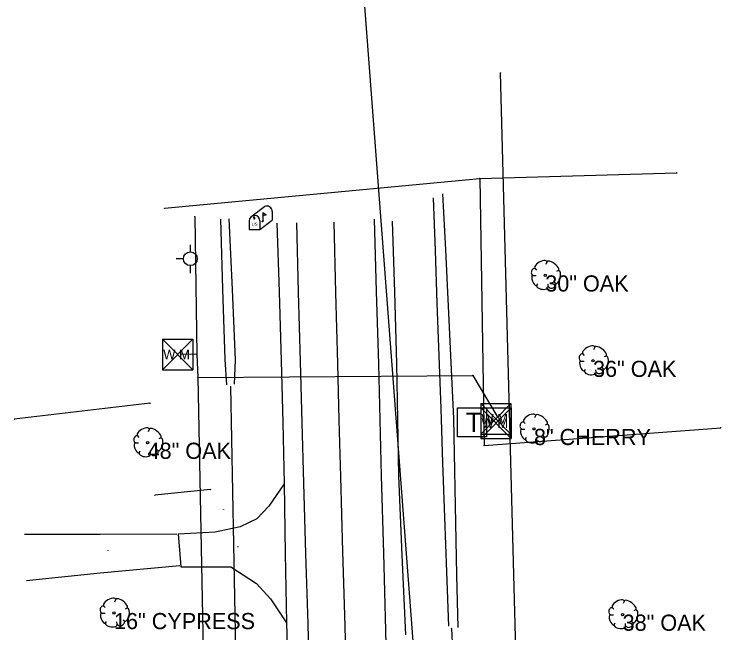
# Model space of a CAD drawing. Extents: x 1930288 to 1941089, y 588389 to 611475.
# Drawn here: x 1930817.5 to 1931036, y 599091.7 to 599283.2 of the extents above; entities that cross this region are included whole.
import ezdxf

# ---------------------------------------------------------------- set-up
doc = ezdxf.new("R2010")
doc.units = 0
for name, color, linetype in [('S_BASELINE', 7, 'Continuous'), ('S_DITCHLINE', 7, 'Continuous'), ('S_DRG_PT_SYM', 7, 'Continuous'), ('S_DRIVEWAY', 7, 'Continuous'), ('S_EDGE_CONCRETE', 7, 'Continuous'), ('S_EDGE_PAVEMENT', 7, 'Continuous'), ('S_GAS_UTILITIES', 7, 'Continuous'), ('S_MAILBOX', 7, 'Continuous'), ('S_MSC_PT_SYM', 7, 'Continuous'), ('S_PAVEMENT_CROWN', 7, 'Continuous'), ('S_SANITARY_SEWER', 7, 'Continuous'), ('S_SHOULDER', 7, 'Continuous'), ('S_SIDE_DRAIN', 7, 'Continuous'), ('S_TELEPHONE_UTILITIES', 7, 'Continuous'), ('S_TREE', 7, 'Continuous'), ('S_TREE_ANNOT', 7, 'Continuous'), ('S_UTILITY_POLE', 7, 'Continuous'), ('S_UTL_PT_SYM', 7, 'Continuous'), ('S_WATER_UTILITIES', 7, 'Continuous')]:
    doc.layers.add(name, color=color, linetype=linetype)

msp = doc.modelspace()

# ---------------------------------------------------------------- linework, layer by layer
at = {"layer": 'S_BASELINE'}
msp.add_line((1930946.09, 599020.44), (1930874, 599969.55), dxfattribs=at)
at = {"layer": 'S_DITCHLINE'}
for points in [[(1930949.94, 599227.59), (1930950.79, 599210.21), (1930951.65, 599192.82), (1930952.5, 599175.44), (1930953.35, 599158.06), (1930953.66, 599141.89), (1930953.97, 599125.73), (1930954.29, 599109.56), (1930954.6, 599093.39)], [(1930951.87, 599093.81), (1930951.27, 599110.66), (1930950.66, 599127.51), (1930950.05, 599144.35), (1930949.45, 599161.2), (1930948.87, 599177.5), (1930948.3, 599193.8), (1930947.72, 599210.1), (1930947.15, 599226.39)], [(1930881.27, 599219.76), (1930881.94, 599198.06), (1930882.62, 599176.35), (1930883.17, 599168.44)], [(1930883.88, 599219.85), (1930884.86, 599198.03), (1930885.84, 599176.21), (1930885.5, 599168.66)]]:
    msp.add_lwpolyline(points, dxfattribs=at)
at = {"layer": 'S_DRG_PT_SYM'}
for points in [[(1930884.4, 599167.97), (1930884.4, 599168.02), (1930884.4, 599167.97), (1930884.35, 599167.97), (1930884.4, 599167.97), (1930884.4, 599167.92), (1930884.4, 599167.97), (1930884.45, 599167.97)], [(1930952.67, 599093.04), (1930952.67, 599093.09), (1930952.67, 599093.04), (1930952.62, 599093.04), (1930952.67, 599093.04), (1930952.67, 599092.99), (1930952.67, 599093.04), (1930952.72, 599093.04)]]:
    msp.add_lwpolyline(points, dxfattribs=at)
at = {"layer": 'S_DRIVEWAY'}
msp.add_lwpolyline([(1930900.96, 599137.81), (1930896.26, 599130.93), (1930892.54, 599127.06), (1930887.31, 599124.51), (1930879.65, 599122.87), (1930868.17, 599122.32), (1930868.64, 599117.39), (1930868.96, 599112.21), (1930884.48, 599112.12), (1930892.44, 599106.96), (1930896.71, 599102.29), (1930901.66, 599094.84)], dxfattribs=at)
at = {"layer": 'S_EDGE_CONCRETE'}
for points in [[(1930867.74, 599122.23), (1930844.04, 599122.22), (1930820.71, 599122.19)], [(1930821.26, 599107.91), (1930844.04, 599110.3), (1930868.67, 599112.58)]]:
    msp.add_lwpolyline(points, dxfattribs=at)
at = {"layer": 'S_EDGE_PAVEMENT'}
for points in [[(1930904.72, 599218.64), (1930905.3, 599197.16), (1930905.89, 599175.68), (1930906.4, 599156.86), (1930906.92, 599138.04), (1930907.58, 599116.33), (1930908.24, 599094.62), (1930908.7, 599076.29)], [(1930928.79, 599219.79), (1930929.44, 599197.4), (1930930.09, 599175.01), (1930930.52, 599157.68), (1930930.96, 599140.35), (1930931.64, 599116.39), (1930932.32, 599092.44), (1930932.75, 599074.74)]]:
    msp.add_lwpolyline(points, dxfattribs=at)
at = {"layer": 'S_GAS_UTILITIES'}
for p, q in [((1930961.45, 599232.36), (1931022.34, 599234.07)), ((1930864.01, 599223.13), (1930961.45, 599232.36)), ((1930961.45, 599232.36), (1930962.79, 599149.74)), ((1930962.79, 599149.74), (1931035.92, 599155.19)), ((1930878.21, 599136.1), (1930860.97, 599134.33))]:
    msp.add_line(p, q, dxfattribs=at)
at = {"layer": 'S_MAILBOX'}
for p, q in [((1930890.7, 599220.51), (1930894.83, 599223.62)), ((1930894.32, 599221.8), (1930894.32, 599219.09)), ((1930897.27, 599222.15), (1930897.27, 599219.43)), ((1930890.15, 599219.24), (1930890.15, 599216.52)), ((1930893.47, 599216.52), (1930897.27, 599219.43)), ((1930893.47, 599219.24), (1930893.47, 599216.52)), ((1930890.15, 599216.52), (1930893.47, 599216.52))]:
    msp.add_line(p, q, dxfattribs=at)
for points in [[(1930891.33, 599220.35), (1930891.55, 599220.21), (1930891.55, 599219.83), (1930891.86, 599219.83), (1930891.86, 599220.19), (1930891.66, 599220.44), (1930891.33, 599220.38)], [(1930894.32, 599221.8), (1930895.42, 599221.14), (1930894.32, 599220.79)]]:
    msp.add_lwpolyline(points, dxfattribs=at)
for centre, end in [((1930895.6, 599222.15), 117.5718), ((1930891.81, 599219.24), 180)]:
    msp.add_arc(centre, 1.66, 0, end, dxfattribs=at)
msp.add_ellipse((1930894.32, 599219.09), major_axis=(0.145, 0.132), ratio=0.564646, dxfattribs=at)
at = {"layer": 'S_MSC_PT_SYM'}
for points in [[(1930859.48, 599162.79), (1930859.48, 599162.84), (1930859.48, 599162.79), (1930859.43, 599162.79), (1930859.48, 599162.79), (1930859.48, 599162.74), (1930859.48, 599162.79), (1930859.53, 599162.79)], [(1930817.52, 599157.86), (1930817.52, 599157.91), (1930817.52, 599157.86), (1930817.47, 599157.86), (1930817.52, 599157.86), (1930817.52, 599157.81), (1930817.52, 599157.86), (1930817.57, 599157.86)], [(1930846.44, 599117.27), (1930846.44, 599117.32), (1930846.44, 599117.27), (1930846.39, 599117.27), (1930846.44, 599117.27), (1930846.44, 599117.22), (1930846.44, 599117.27), (1930846.49, 599117.27)], [(1930886.68, 599118.36), (1930886.68, 599118.41), (1930886.68, 599118.36), (1930886.63, 599118.36), (1930886.68, 599118.36), (1930886.68, 599118.31), (1930886.68, 599118.36), (1930886.73, 599118.36)]]:
    msp.add_lwpolyline(points, dxfattribs=at)
at = {"layer": 'S_PAVEMENT_CROWN'}
msp.add_lwpolyline([(1930916.29, 599218.8), (1930916.85, 599196.95), (1930917.41, 599175.1), (1930917.89, 599157.55), (1930918.37, 599139.99), (1930919.03, 599116.95), (1930919.68, 599093.9), (1930920.14, 599075.83)], dxfattribs=at)
at = {"layer": 'S_SANITARY_SEWER'}
msp.add_line((1930979.26, 598838.38), (1930967.81, 599265.02), dxfattribs=at)
at = {"layer": 'S_SHOULDER'}
for points in [[(1930898.7, 599218.51), (1930899.39, 599197.23), (1930900.07, 599175.94), (1930900.52, 599156.88), (1930900.96, 599137.81), (1930901.31, 599116.32), (1930901.66, 599094.84), (1930902.24, 599076.43)], [(1930934.34, 599219.18), (1930935.02, 599197.13), (1930935.7, 599175.08), (1930935.99, 599157.72), (1930936.28, 599140.36), (1930937.38, 599115.75), (1930938.49, 599091.15)]]:
    msp.add_lwpolyline(points, dxfattribs=at)
at = {"layer": 'S_SIDE_DRAIN'}
for p, q in [((1930884.4, 599167.97), (1930886.94, 599030.09)), ((1930952.67, 599093.04), (1930953.96, 599068.83))]:
    msp.add_line(p, q, dxfattribs=at)
at = {"layer": 'S_TELEPHONE_UTILITIES'}
msp.add_lwpolyline([(1930954.56, 599152.37), (1930954.56, 599161.37), (1930963.56, 599161.37), (1930963.56, 599152.37)], close=True, dxfattribs=at)
at = {"layer": 'S_TREE'}
for p, q in [((1930982.23, 599206.61), (1930981.84, 599205.75)), ((1930978.43, 599204.59), (1930978.93, 599204.01)), ((1930985.79, 599203.82), (1930985.13, 599203.54)), ((1930977.77, 599202.27), (1930978.89, 599202.27)), ((1930978.93, 599199.09), (1930979.4, 599199.79)), ((1930982.61, 599198.82), (1930982.54, 599199.59)), ((1930985.02, 599199.71), (1930984.55, 599200.13)), ((1930997, 599180.18), (1930996.61, 599179.33)), ((1930993.2, 599178.16), (1930993.71, 599177.58)), ((1931000.57, 599177.39), (1930999.91, 599177.12)), ((1930992.55, 599175.84), (1930993.67, 599175.84)), ((1930993.71, 599172.66), (1930994.17, 599173.36)), ((1930997.39, 599172.39), (1930997.31, 599173.16)), ((1930999.79, 599173.28), (1930999.33, 599173.71)), ((1930859.48, 599162.79), (1930817.52, 599157.86)), ((1930978.73, 599159.09), (1930978.35, 599158.24)), ((1930974.94, 599157.08), (1930975.44, 599156.5)), ((1930859.29, 599154.83), (1930858.9, 599153.97)), ((1930974.28, 599154.75), (1930975.4, 599154.75)), ((1930982.3, 599156.3), (1930981.64, 599156.03)), ((1930855.49, 599152.81), (1930855.99, 599152.23)), ((1930975.44, 599151.57), (1930975.9, 599152.27)), ((1930981.52, 599152.19), (1930981.06, 599152.62)), ((1930854.83, 599150.49), (1930855.95, 599150.49)), ((1930862.85, 599152.04), (1930862.19, 599151.77)), ((1930979.12, 599151.3), (1930979.04, 599152.08)), ((1930855.99, 599147.31), (1930856.46, 599148.01)), ((1930862.08, 599147.93), (1930861.61, 599148.36)), ((1930859.67, 599147.04), (1930859.6, 599147.81)), ((1930848.9, 599102.12), (1930848.51, 599101.27)), ((1930845.1, 599100.11), (1930845.61, 599099.53)), ((1931006.15, 599101.63), (1931005.76, 599100.77)), ((1930844.44, 599097.78), (1930845.57, 599097.78)), ((1930852.46, 599099.33), (1930851.81, 599099.06)), ((1931002.35, 599099.61), (1931002.85, 599099.03)), ((1931009.71, 599098.84), (1931009.05, 599098.57)), ((1930851.69, 599095.23), (1930851.22, 599095.65)), ((1931001.69, 599097.29), (1931002.82, 599097.29)), ((1930845.61, 599094.61), (1930846.07, 599095.3)), ((1930849.29, 599094.34), (1930849.21, 599095.11)), ((1931002.85, 599094.11), (1931003.32, 599094.81)), ((1931006.54, 599093.84), (1931006.46, 599094.61)), ((1931008.94, 599094.73), (1931008.47, 599095.16))]:
    msp.add_line(p, q, dxfattribs=at)
for centre in [(1930981.67, 599202.36), (1930996.44, 599175.93), (1930978.17, 599154.85), (1930858.73, 599150.58), (1930848.34, 599097.88), (1931005.59, 599097.38)]:
    msp.add_circle(centre, 0.341, dxfattribs=at)
for centre, major_axis, ratio, start_param, end_param in [((1930980.33, 599205.56), (1.86, 1.08), 0.471018, 0, 3.141593), ((1930983.99, 599205.24), (-1.81, 1.36), 0.405113, 3.141593, 6.283186), ((1930978.1, 599203.45), (0.31, 1.03), 0.646762, 0, 3.141593), ((1930985.34, 599201.83), (0.46, 2.04), 0.482994, 3.141593, 6.283185), ((1930978.4, 599200.8), (-0.61, 1.6), 0.420543, 6.283185, 9.424777), ((1930980.86, 599199.02), (-1.83, 0.19), 0.529943, 0, 3.141593), ((1930983.82, 599199.31), (1.09, 0.46), 0.711534, 3.141592, 6.283185), ((1930995.11, 599179.14), (1.86, 1.08), 0.471018, 0, 3.141593), ((1930998.76, 599178.81), (-1.81, 1.36), 0.405113, 3.141593, 6.283186), ((1930992.87, 599177.02), (0.31, 1.03), 0.646762, 0, 3.141593), ((1931000.12, 599175.4), (0.46, 2.04), 0.482994, 3.141593, 6.283185), ((1930993.18, 599174.37), (-0.61, 1.6), 0.420543, 6.283185, 9.424777), ((1930995.64, 599172.59), (-1.83, 0.19), 0.529943, 0, 3.141593), ((1930998.6, 599172.88), (1.09, 0.46), 0.711534, 3.141592, 6.283185), ((1930976.84, 599158.05), (1.86, 1.08), 0.471018, 0, 3.141593), ((1930980.49, 599157.73), (-1.81, 1.36), 0.405113, 3.141593, 6.283186), ((1930974.6, 599155.93), (0.31, 1.03), 0.646762, 0, 3.141593), ((1930857.39, 599153.78), (1.86, 1.08), 0.471018, 0, 3.141593), ((1930861.05, 599153.46), (-1.81, 1.36), 0.405113, 3.141593, 6.283186), ((1930974.91, 599153.28), (-0.61, 1.6), 0.420543, 6.283185, 9.424777), ((1930981.85, 599154.32), (0.46, 2.04), 0.482994, 3.141593, 6.283185), ((1930855.16, 599151.67), (0.31, 1.03), 0.646762, 0, 3.141593), ((1930980.33, 599151.8), (1.09, 0.46), 0.711534, 3.141592, 6.283185), ((1930855.46, 599149.02), (-0.61, 1.6), 0.420543, 6.283185, 9.424777), ((1930862.4, 599150.05), (0.46, 2.04), 0.482994, 3.141593, 6.283185), ((1930977.37, 599151.5), (-1.83, 0.19), 0.529943, 0, 3.141593), ((1930860.88, 599147.53), (1.09, 0.46), 0.711534, 3.141592, 6.283185), ((1930857.92, 599147.24), (-1.83, 0.19), 0.529943, 0, 3.141593), ((1930847, 599101.08), (1.86, 1.08), 0.471018, 0, 3.141593), ((1930850.66, 599100.76), (-1.81, 1.36), 0.405113, 3.141593, 6.283186), ((1931004.25, 599100.58), (1.86, 1.08), 0.471018, 0, 3.141593), ((1931007.91, 599100.26), (-1.81, 1.36), 0.405113, 3.141593, 6.283186), ((1930844.77, 599098.97), (0.31, 1.03), 0.646762, 0, 3.141593), ((1930845.08, 599096.32), (-0.61, 1.6), 0.420543, 6.283185, 9.424777), ((1930852.02, 599097.35), (0.46, 2.04), 0.482994, 3.141593, 6.283185), ((1931002.02, 599098.47), (0.31, 1.03), 0.646762, 0, 3.141593), ((1931009.26, 599096.85), (0.46, 2.04), 0.482994, 3.141593, 6.283185), ((1931002.32, 599095.82), (-0.61, 1.6), 0.420543, 6.283185, 9.424777), ((1930847.54, 599094.54), (-1.83, 0.19), 0.529943, 0, 3.141593), ((1930850.49, 599094.83), (1.09, 0.46), 0.711534, 3.141592, 6.283185), ((1931004.79, 599094.04), (-1.83, 0.19), 0.529943, 0, 3.141593), ((1931007.74, 599094.33), (1.09, 0.46), 0.711534, 3.141592, 6.283185)]:
    msp.add_ellipse(centre, major_axis=major_axis, ratio=ratio, start_param=start_param, end_param=end_param, dxfattribs=at)
at = {"layer": 'S_UTILITY_POLE'}
for p, q in [((1930871.95, 599209.6), (1930871.95, 599211.85)), ((1930869.86, 599207.47), (1930867.53, 599207.47)), ((1930872.03, 599203.05), (1930872.03, 599205.38))]:
    msp.add_line(p, q, dxfattribs=at)
msp.add_circle((1930871.95, 599207.49), 2.13, dxfattribs=at)
at = {"layer": 'S_UTL_PT_SYM'}
for points in [[(1930967.81, 599265.02), (1930967.81, 599265.07), (1930967.81, 599265.02), (1930967.76, 599265.02), (1930967.81, 599265.02), (1930967.81, 599264.97), (1930967.81, 599265.02), (1930967.86, 599265.02)], [(1931022.34, 599234.07), (1931022.34, 599234.12), (1931022.34, 599234.07), (1931022.29, 599234.07), (1931022.34, 599234.07), (1931022.34, 599234.02), (1931022.34, 599234.07), (1931022.39, 599234.07)], [(1930961.45, 599232.36), (1930961.45, 599232.41), (1930961.45, 599232.36), (1930961.4, 599232.36), (1930961.45, 599232.36), (1930961.45, 599232.31), (1930961.45, 599232.36), (1930961.5, 599232.36)], [(1930864.01, 599223.13), (1930864.01, 599223.18), (1930864.01, 599223.13), (1930863.96, 599223.13), (1930864.01, 599223.13), (1930864.01, 599223.08), (1930864.01, 599223.13), (1930864.06, 599223.13)], [(1930873.32, 599220.52), (1930873.32, 599220.57), (1930873.32, 599220.52), (1930873.27, 599220.52), (1930873.32, 599220.52), (1930873.32, 599220.47), (1930873.32, 599220.52), (1930873.37, 599220.52)], [(1930869.17, 599178), (1930869.17, 599178.05), (1930869.17, 599178), (1930869.12, 599178), (1930869.17, 599178), (1930869.17, 599177.95), (1930869.17, 599178), (1930869.22, 599178)], [(1930873.93, 599177.85), (1930873.93, 599177.9), (1930873.93, 599177.85), (1930873.88, 599177.85), (1930873.93, 599177.85), (1930873.93, 599177.8), (1930873.93, 599177.85), (1930873.98, 599177.85)], [(1930873.93, 599177.85), (1930873.93, 599177.9), (1930873.93, 599177.85), (1930873.88, 599177.85), (1930873.93, 599177.85), (1930873.93, 599177.8), (1930873.93, 599177.85), (1930873.98, 599177.85)], [(1930874.23, 599170.75), (1930874.23, 599170.8), (1930874.23, 599170.75), (1930874.18, 599170.75), (1930874.23, 599170.75), (1930874.23, 599170.7), (1930874.23, 599170.75), (1930874.28, 599170.75)], [(1930874.23, 599170.75), (1930874.23, 599170.8), (1930874.23, 599170.75), (1930874.18, 599170.75), (1930874.23, 599170.75), (1930874.23, 599170.7), (1930874.23, 599170.75), (1930874.28, 599170.75)], [(1930959.27, 599171.38), (1930959.27, 599171.43), (1930959.27, 599171.38), (1930959.22, 599171.38), (1930959.27, 599171.38), (1930959.27, 599171.33), (1930959.27, 599171.38), (1930959.32, 599171.38)], [(1930966.66, 599158.85), (1930966.66, 599158.9), (1930966.66, 599158.85), (1930966.61, 599158.85), (1930966.66, 599158.85), (1930966.66, 599158.8), (1930966.66, 599158.85), (1930966.71, 599158.85)], [(1931035.92, 599155.19), (1931035.92, 599155.24), (1931035.92, 599155.19), (1931035.87, 599155.19), (1931035.92, 599155.19), (1931035.92, 599155.14), (1931035.92, 599155.19), (1931035.97, 599155.19)], [(1930962.79, 599149.74), (1930962.79, 599149.79), (1930962.79, 599149.74), (1930962.74, 599149.74), (1930962.79, 599149.74), (1930962.79, 599149.69), (1930962.79, 599149.74), (1930962.84, 599149.74)], [(1930878.21, 599136.1), (1930878.21, 599136.15), (1930878.21, 599136.1), (1930878.16, 599136.1), (1930878.21, 599136.1), (1930878.21, 599136.05), (1930878.21, 599136.1), (1930878.26, 599136.1)], [(1930860.97, 599134.33), (1930860.97, 599134.38), (1930860.97, 599134.33), (1930860.92, 599134.33), (1930860.97, 599134.33), (1930860.97, 599134.28), (1930860.97, 599134.33), (1930861.02, 599134.33)], [(1930882.2, 599129.99), (1930882.2, 599130.04), (1930882.2, 599129.99), (1930882.15, 599129.99), (1930882.2, 599129.99), (1930882.2, 599129.94), (1930882.2, 599129.99), (1930882.25, 599129.99)]]:
    msp.add_lwpolyline(points, dxfattribs=at)
at = {"layer": 'S_WATER_UTILITIES'}
for p, q in [((1930873.32, 599220.52), (1930873.93, 599177.85)), ((1930863.36, 599182.63), (1930872.7, 599182.63)), ((1930863.36, 599182.63), (1930863.36, 599173.13)), ((1930863.36, 599182.63), (1930872.7, 599173.13)), ((1930872.7, 599182.63), (1930863.36, 599173.13)), ((1930872.7, 599182.63), (1930872.7, 599173.13)), ((1930873.93, 599177.85), (1930869.17, 599178)), ((1930873.93, 599177.85), (1930874.23, 599170.75)), ((1930863.36, 599173.13), (1930872.7, 599173.13)), ((1930874.23, 599170.75), (1930959.27, 599171.38)), ((1930874.23, 599170.75), (1930877.25, 599023.82)), ((1930959.27, 599171.38), (1930966.66, 599158.85)), ((1930961.74, 599162.73), (1930971.08, 599162.73)), ((1930961.74, 599162.73), (1930961.74, 599153.23)), ((1930961.74, 599162.73), (1930971.08, 599153.23)), ((1930971.08, 599162.73), (1930961.74, 599153.23)), ((1930961.79, 599161.36), (1930971.13, 599161.36)), ((1930961.79, 599161.36), (1930961.79, 599151.87)), ((1930961.79, 599161.36), (1930971.13, 599151.87)), ((1930971.13, 599161.36), (1930961.79, 599151.87)), ((1930971.08, 599162.73), (1930971.08, 599153.23)), ((1930971.13, 599161.36), (1930971.13, 599151.87)), ((1930961.74, 599153.23), (1930971.08, 599153.23)), ((1930961.79, 599151.87), (1930971.13, 599151.87))]:
    msp.add_line(p, q, dxfattribs=at)

# ---------------------------------------------------------------- texts
at = {"layer": 'S_MAILBOX'}
msp.add_text('US', height=0.96, rotation=360, dxfattribs=at).set_placement((1930890.91, 599217.72))
at = {"layer": 'S_TELEPHONE_UTILITIES'}
msp.add_text('T', height=6, rotation=360, dxfattribs=at).set_placement((1930957.12, 599153.87))
at = {"layer": 'S_TREE_ANNOT'}
for s, p in [('30" OAK', (1930981.67, 599197.36)), ('36" OAK', (1930996.44, 599170.93)), ('8" CHERRY', (1930978.17, 599149.85)), ('48" OAK', (1930858.73, 599145.58)), ('16" CYPRESS', (1930848.34, 599092.88)), ('38" OAK', (1931005.59, 599092.38))]:
    msp.add_text(s, height=5, dxfattribs=at).set_placement(p)
at = {"layer": 'S_WATER_UTILITIES'}
for p in [(1930863.57, 599176.39), (1930961.95, 599156.49), (1930961.99, 599155.13)]:
    msp.add_text('W M', height=3, rotation=360, dxfattribs=at).set_placement(p)

doc.saveas('drawing.dxf')
